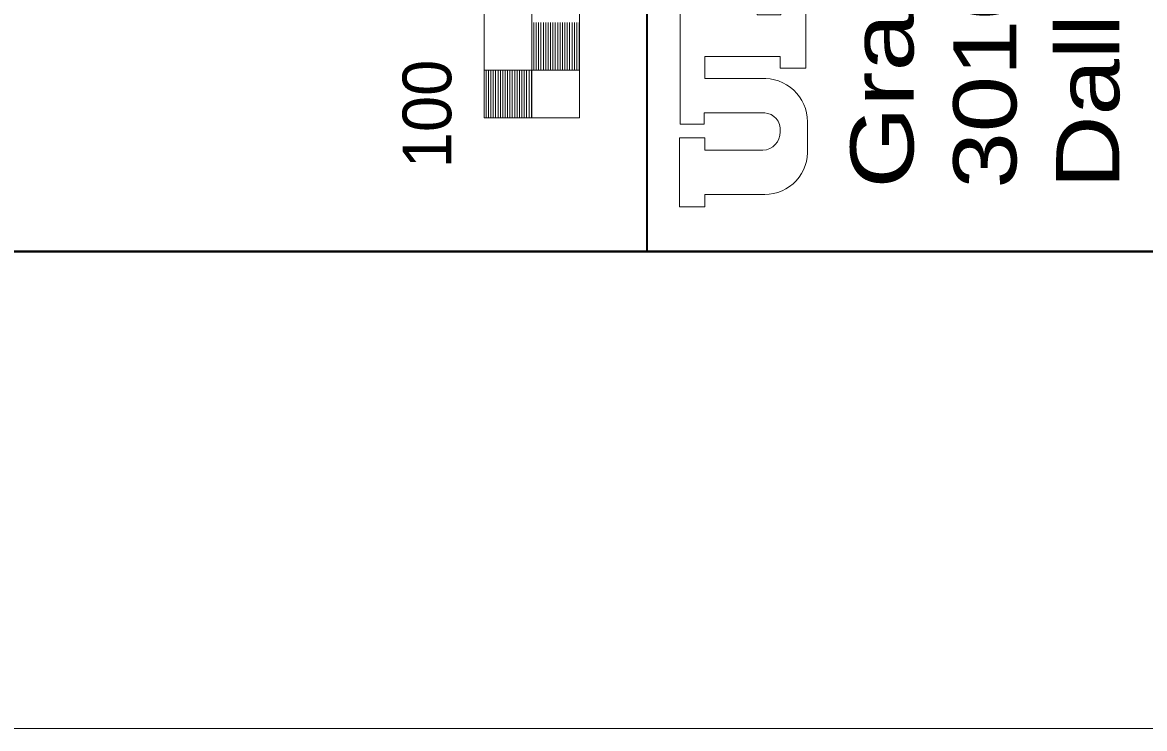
# Model space of a CAD drawing. Extents: x 2363323 to 2367082, y 6956018 to 6980837.
# Drawn here: x 2366471.6 to 2366706.6, y 6957200.9 to 6957348.9 of the extents above; entities that cross this region are included whole.
import ezdxf
from ezdxf.enums import TextEntityAlignment as Align

# ---------------------------------------------------------------- set-up
doc = ezdxf.new("R2010")
doc.units = 0
doc.header["$LTSCALE"] = 4.1
for name, color, linetype, lineweight in [('61', 7, 'Continuous', 40), ('62', 7, 'Continuous', 13), ('63', 7, 'Continuous', 13)]:
    doc.layers.add(name, color=color, linetype=linetype, lineweight=lineweight)

msp = doc.modelspace()

# ---------------------------------------------------------------- linework, layer by layer
at = {"layer": '61'}
msp.add_line((2366823.34, 6957300.912), (2363423.186, 6957300.912), dxfattribs=at)
msp.add_line((2366823.34, 6957300.912), (2363423.186, 6957300.912), dxfattribs=at)
at = {"layer": '61', "lineweight": 13}
msp.add_lwpolyline([(2366923.344, 6957200.912), (2363323.182, 6957200.912), (2363323.182, 6980256.082)], dxfattribs=at)
at = {"layer": '62', "lineweight": 35}
msp.add_line((2366602.353, 6957951.933), (2366602.354, 6957300.911), dxfattribs=at)
at = {"layer": '62'}
for p, q in [((2366568.268, 6957328.893), (2366568.268, 6957728.93)), ((2366578.269, 6957328.894), (2366578.269, 6957728.93)), ((2366588.269, 6957328.893), (2366588.27, 6957728.93)), ((2366578.701, 6957338.894), (2366578.701, 6957348.894)), ((2366579.201, 6957338.894), (2366579.201, 6957348.893)), ((2366579.701, 6957338.894), (2366579.702, 6957348.894)), ((2366580.201, 6957338.894), (2366580.201, 6957348.894)), ((2366580.701, 6957338.894), (2366580.701, 6957348.895)), ((2366581.201, 6957338.895), (2366581.202, 6957348.894)), ((2366581.701, 6957338.893), (2366581.701, 6957348.894)), ((2366582.201, 6957338.894), (2366582.202, 6957348.893)), ((2366582.701, 6957338.894), (2366582.701, 6957348.893)), ((2366583.201, 6957338.893), (2366583.201, 6957348.894)), ((2366583.701, 6957338.894), (2366583.702, 6957348.894)), ((2366584.202, 6957338.894), (2366584.201, 6957348.893)), ((2366584.702, 6957338.894), (2366584.702, 6957348.894)), ((2366585.203, 6957338.894), (2366585.203, 6957348.894)), ((2366585.702, 6957338.893), (2366585.703, 6957348.895)), ((2366586.202, 6957338.894), (2366586.203, 6957348.893)), ((2366586.703, 6957338.893), (2366586.703, 6957348.894)), ((2366587.203, 6957338.894), (2366587.202, 6957348.894)), ((2366587.703, 6957338.893), (2366587.702, 6957348.894)), ((2366588.203, 6957338.893), (2366588.202, 6957348.895)), ((2366568.269, 6957338.894), (2366578.269, 6957338.894)), ((2366568.699, 6957328.893), (2366568.701, 6957338.895)), ((2366569.201, 6957328.894), (2366569.201, 6957338.895)), ((2366569.701, 6957328.893), (2366569.701, 6957338.895)), ((2366570.201, 6957328.894), (2366570.201, 6957338.894)), ((2366570.701, 6957328.893), (2366570.701, 6957338.894)), ((2366571.201, 6957328.894), (2366571.201, 6957338.894)), ((2366571.701, 6957328.893), (2366571.701, 6957338.894)), ((2366572.201, 6957328.893), (2366572.201, 6957338.895)), ((2366572.701, 6957328.894), (2366572.701, 6957338.894)), ((2366573.201, 6957328.893), (2366573.201, 6957338.894)), ((2366573.701, 6957328.893), (2366573.701, 6957338.894)), ((2366574.201, 6957328.893), (2366574.2, 6957338.894)), ((2366574.701, 6957328.893), (2366574.7, 6957338.895)), ((2366575.201, 6957328.894), (2366575.2, 6957338.894)), ((2366575.701, 6957328.893), (2366575.7, 6957338.895)), ((2366576.201, 6957328.894), (2366576.201, 6957338.895)), ((2366576.701, 6957328.894), (2366576.7, 6957338.895)), ((2366577.2, 6957328.893), (2366577.201, 6957338.895)), ((2366577.7, 6957328.893), (2366577.7, 6957338.894)), ((2366578.2, 6957328.893), (2366578.2, 6957338.895)), ((2366578.269, 6957338.894), (2366588.27, 6957338.894)), ((2366568.268, 6957328.893), (2366578.269, 6957328.894)), ((2366636.026, 6957328.079), (2366636.023, 6957322.527)), ((2366630.32, 6957325.969), (2366630.32, 6957326.829))]:
    msp.add_line(p, q, dxfattribs=at)
for points in [[(2366633.978, 6957374.261), (2366635.7, 6957374.261), (2366635.7, 6957358.128), (2366625.477, 6957352.75), (2366625.477, 6957350.491), (2366630.427, 6957350.491), (2366630.427, 6957353.18), (2366635.7, 6957353.18), (2366635.7, 6957339.306), (2366630.32, 6957339.306), (2366630.32, 6957341.779), (2366614.502, 6957341.779), (2366614.502, 6957337.154), (2366626.338, 6957337.154)], [(2366626.338, 6957329.948), (2366614.394, 6957329.948), (2366614.394, 6957327.582), (2366609.337, 6957327.582), (2366609.337, 6957356.622)], [(2366627.091, 6957312.847), (2366614.502, 6957312.847), (2366614.502, 6957310.266), (2366609.229, 6957310.266), (2366609.229, 6957324.678), (2366614.502, 6957324.678), (2366614.502, 6957322.097), (2366626.661, 6957322.097)]]:
    msp.add_lwpolyline(points, dxfattribs=at)
msp.add_lwpolyline([(2366588.269, 6957328.893), (2366588.27, 6957338.894), (2366568.269, 6957338.894), (2366568.268, 6957328.893)], close=True, dxfattribs=at)
for centre, radius, start, end in [((2366626.875, 6957328.019), 9.151, 0.37291, 93.36394), ((2366626.757, 6957326.382), 3.591, 7.15138, 96.69605), ((2366626.513, 6957325.901), 3.807, 272.2293, 1.01817), ((2366627.1, 6957321.799), 8.952, 269.94292, 4.66557)]:
    msp.add_arc(centre, radius, start, end, dxfattribs=at)
at = {"layer": '63', "lineweight": 35}
msp.add_line((2366602.353, 6957951.933), (2366602.354, 6957300.911), dxfattribs=at)
at = {"layer": '63'}
for p, q in [((2366568.268, 6957328.893), (2366568.268, 6957728.93)), ((2366578.269, 6957328.894), (2366578.269, 6957728.93)), ((2366588.269, 6957328.893), (2366588.27, 6957728.93)), ((2366578.701, 6957338.894), (2366578.701, 6957348.894)), ((2366579.201, 6957338.894), (2366579.201, 6957348.893)), ((2366579.701, 6957338.894), (2366579.702, 6957348.894)), ((2366580.201, 6957338.894), (2366580.201, 6957348.894)), ((2366580.701, 6957338.894), (2366580.701, 6957348.895)), ((2366581.201, 6957338.895), (2366581.202, 6957348.894)), ((2366581.701, 6957338.893), (2366581.701, 6957348.894)), ((2366582.201, 6957338.894), (2366582.202, 6957348.893)), ((2366582.701, 6957338.894), (2366582.701, 6957348.893)), ((2366583.201, 6957338.893), (2366583.201, 6957348.894)), ((2366583.701, 6957338.894), (2366583.702, 6957348.894)), ((2366584.202, 6957338.894), (2366584.201, 6957348.893)), ((2366584.702, 6957338.894), (2366584.702, 6957348.894)), ((2366585.203, 6957338.894), (2366585.203, 6957348.894)), ((2366585.702, 6957338.893), (2366585.703, 6957348.895)), ((2366586.202, 6957338.894), (2366586.203, 6957348.893)), ((2366586.703, 6957338.893), (2366586.703, 6957348.894)), ((2366587.203, 6957338.894), (2366587.202, 6957348.894)), ((2366587.703, 6957338.893), (2366587.702, 6957348.894)), ((2366588.203, 6957338.893), (2366588.202, 6957348.895)), ((2366568.269, 6957338.894), (2366578.269, 6957338.894)), ((2366568.699, 6957328.893), (2366568.701, 6957338.895)), ((2366569.201, 6957328.894), (2366569.201, 6957338.895)), ((2366569.701, 6957328.893), (2366569.701, 6957338.895)), ((2366570.201, 6957328.894), (2366570.201, 6957338.894)), ((2366570.701, 6957328.893), (2366570.701, 6957338.894)), ((2366571.201, 6957328.894), (2366571.201, 6957338.894)), ((2366571.701, 6957328.893), (2366571.701, 6957338.894)), ((2366572.201, 6957328.893), (2366572.201, 6957338.895)), ((2366572.701, 6957328.894), (2366572.701, 6957338.894)), ((2366573.201, 6957328.893), (2366573.201, 6957338.894)), ((2366573.701, 6957328.893), (2366573.701, 6957338.894)), ((2366574.201, 6957328.893), (2366574.2, 6957338.894)), ((2366574.701, 6957328.893), (2366574.7, 6957338.895)), ((2366575.201, 6957328.894), (2366575.2, 6957338.894)), ((2366575.701, 6957328.893), (2366575.7, 6957338.895)), ((2366576.201, 6957328.894), (2366576.201, 6957338.895)), ((2366576.701, 6957328.894), (2366576.7, 6957338.895)), ((2366577.2, 6957328.893), (2366577.201, 6957338.895)), ((2366577.7, 6957328.893), (2366577.7, 6957338.894)), ((2366578.2, 6957328.893), (2366578.2, 6957338.895)), ((2366578.269, 6957338.894), (2366588.27, 6957338.894)), ((2366568.268, 6957328.893), (2366578.269, 6957328.894))]:
    msp.add_line(p, q, dxfattribs=at)
msp.add_lwpolyline([(2366588.269, 6957328.893), (2366588.27, 6957338.894), (2366568.269, 6957338.894), (2366568.268, 6957328.893)], close=True, dxfattribs=at)

# ---------------------------------------------------------------- texts
at = {"layer": '62'}
for s, width, p in [('3010 LBJ Freeway, Suite 1300', 1.2, (2366679.786, 6957314.081)), ('Dallas, Texas 75234', 1.2, (2366701.333, 6957314.081)), ('Graystone Centre', 1.25, (2366658.238, 6957314.081))]:
    msp.add_text(s, height=13.22, rotation=90, dxfattribs=dict(at, width=width)).set_placement(p)
msp.add_text('100', height=10.2, rotation=90, dxfattribs=at).set_placement((2366561.411, 6957329.706), align=Align.CENTER)
at = {"layer": '63'}
msp.add_text('100', height=10.2, rotation=90, dxfattribs=at).set_placement((2366561.411, 6957329.706), align=Align.CENTER)

doc.saveas('drawing.dxf')
